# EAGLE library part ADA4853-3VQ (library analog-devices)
Low Power, Rail-to-Rail Output, Video Op Amps with Ultralow Power Source: http://www.analog.com/static/imported-files/data_sheets/ADA4853-1_4853-2_4853-3.pdf
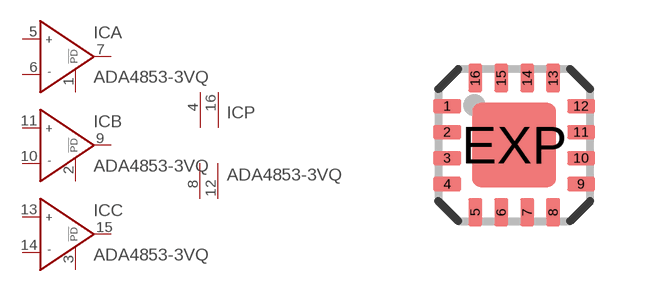
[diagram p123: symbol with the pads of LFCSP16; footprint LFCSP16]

Designator prefix IC; gates A=OP_PD B=OP_PD C=OP_PD P=PWR+-2

## ADA4853-3VQ (OC_FARNELL: unknown; OC_NEWARK: unknown)  [LFCSP16]
1  A:!POWERDOWN  pas
2  B:!POWERDOWN  pas
3  C:!POWERDOWN  pas
4  P:V+  pwr
5  A:IN+  in
6  A:IN-  in
7  A:OUT  out
8  P:V-  pwr
9  B:OUT  out
10  B:IN-  in
11  B:IN+  in
12  P:V-  pwr
13  C:IN+  in
14  C:IN-  in
15  C:OUT  out
16  P:V+  pwr

## Footprint LFCSP16 (pad centres in mm)
16-Terminal Leadless Frame Chip Scale Package [LFCSP] (CP) Source: Analog Devices .. 780914713ADD8704_0.pdf
smd 0.7 x 0.35: 1 -1.675,0.975; 2 -1.675,0.325; 3 -1.675,-0.325; 4 -1.675,-0.975; 9 1.675,-0.975; 10 1.675,-0.325; 11 1.675,0.325; 12 1.675,0.975
smd 0.35 x 0.7: 5 -0.975,-1.675; 6 -0.325,-1.675; 7 0.325,-1.675; 8 0.975,-1.675; 13 0.975,1.675; 14 0.325,1.675; 15 -0.325,1.675; 16 -0.975,1.675
smd 2.1 x 2.1: EXP 0,0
